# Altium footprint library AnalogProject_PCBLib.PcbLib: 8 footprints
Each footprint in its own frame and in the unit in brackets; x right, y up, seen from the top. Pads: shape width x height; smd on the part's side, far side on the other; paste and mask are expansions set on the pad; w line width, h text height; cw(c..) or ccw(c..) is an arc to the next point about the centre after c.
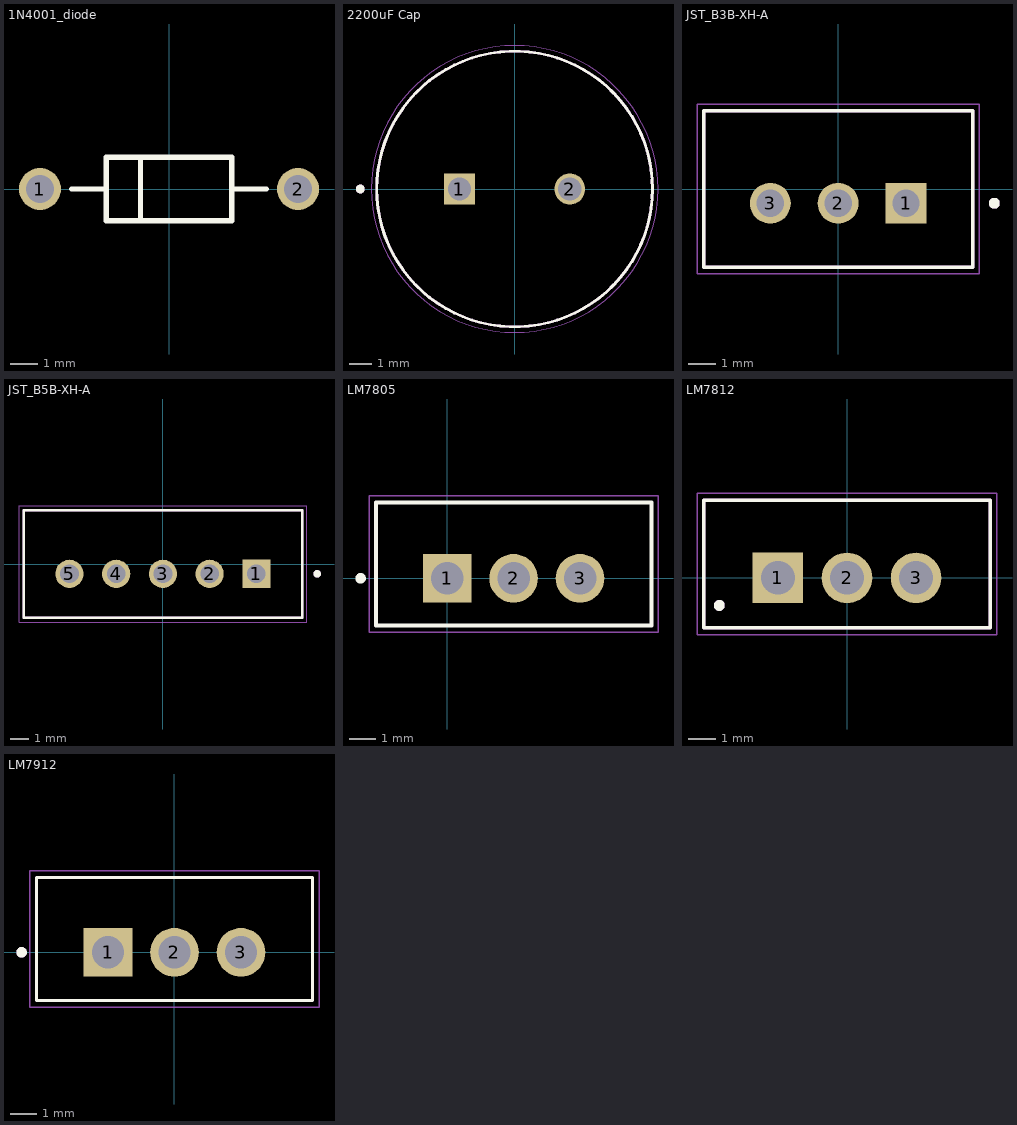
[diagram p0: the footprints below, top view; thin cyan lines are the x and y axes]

## 1N4001_diode [mm] "AXIAL, 2-Leads, Diameter 2.35mm"
height 2.35
pads (2):
  round 1.55 hole 1.05: 1(-4.77,0) 2(4.77,0)
Top Overlay:
  lines w0.2: -3.595,0 -2.325,0 ; -1.055,-1.175 -1.055,1.175 ; 2.325,0 3.595,0 ; -2.325,-1.175 2.325,-1.175 2.325,1.175 -2.325,1.175 -2.325,-1.175

## 2200uF Cap [mm]
pads (2):
  rect 1.4x1.4 hole 1.05: 1(-2.5,0)
  round 1.4 hole 1.05: 2(2.5,0)
Top Overlay:
  circle w0.127: c0,0 r6.25
  circle w0.2: c-7,0 r0.1
Mechanical 13:
  circle w0.127: c0,0 r6.25
  circle w0.2: c-7,0 r0.1
Mechanical 15:
  circle w0.05: c0,0 r6.5
3D body "step_temp.STEP": height 35, standoff -17, extent -6.25,-6.249 6.25,6.249

## JST_B3B-XH-A [mm]
height 7
pads (3):
  rect 1.508x1.508 / inner round 1.508 / far side rect 1.508x1.508 hole 1: 1(2.5,-0.525)
  round 1.508 hole 1: 2(0,-0.525) 3(-2.5,-0.525)
Top Overlay:
  circle w0.2: c5.75,-0.525 r0.1
  lines w0.127: -4.95,-2.875 4.95,-2.875 4.95,2.875 -4.95,2.875 -4.95,-2.875
Mechanical 13:
  circle w0.2: c5.75,-0.525 r0.1
  lines w0.127: -4.95,-2.875 4.95,-2.875 4.95,2.875 -4.95,2.875 -4.95,-2.875
Mechanical 15:
  lines w0.05: -5.2,-3.125 5.2,-3.125 5.2,3.125 -5.2,3.125 -5.2,-3.125
3D body "step_temp.STEP": height 7, standoff -3.4, extent -4.95,-2.875 4.95,2.875

## JST_B5B-XH-A [mm]
height 7
pads (5):
  rect 1.508x1.508 / inner round 1.508 / far side rect 1.508x1.508 hole 1: 1(5,-0.525)
  round 1.508 hole 1: 2(2.5,-0.525) 3(0,-0.525) 4(-2.5,-0.525) 5(-5,-0.525)
Top Overlay:
  circle w0.2: c8.25,-0.525 r0.1
  lines w0.127: -7.45,-2.875 -7.45,2.875 7.45,2.875 7.45,-2.875 -7.45,-2.875
Mechanical 13:
  circle w0.2: c8.25,-0.525 r0.1
  lines w0.127: -7.45,-2.875 -7.45,2.875 7.45,2.875 7.45,-2.875 -7.45,-2.875
Mechanical 15:
  lines w0.05: -7.7,-3.125 -7.7,3.125 7.7,3.125 7.7,-3.125 -7.7,-3.125
3D body "step_temp.STEP": height 7, standoff -3.4, extent -7.45,-2.875 7.45,2.875

## LM7805 [mm]
pads (3):
  rect 1.86x1.86 / inner round 1.86 / far side rect 1.86x1.86 hole 1.24: 1(0,0)
  round 1.86 hole 1.24: 2(2.54,0) 3(5.08,0)
Top Overlay:
  circle w0.2: c-3.31,0 r0.1
  lines w0.152: -2.73,-1.8 -2.73,2.9 7.81,2.9 7.81,-1.8 -2.73,-1.8
Mechanical 13:
  lines w0.127: -2.73,-1.8 -2.73,2.9 7.81,2.9 7.81,-1.8 -2.73,-1.8
Mechanical 15:
  lines w0.05: -2.98,-2.052 8.06,-2.052 8.06,3.148 -2.98,3.148 -2.98,-2.052
3D body "step_temp.STEP": height 20.4, standoff -9.94, extent -2.54,-2.143 7.62,2.207

## LM7812 [mm]
pads (3):
  rect 1.86x1.86 / inner round 1.86 / far side rect 1.86x1.86 hole 1.24: 1(-2.54,0)
  round 1.86 hole 1.24: 2(0,0) 3(2.54,0)
Top Overlay:
  circle w0.2: c-4.699,-1.016 r0.1
  lines w0.127: -5.27,-1.84 5.27,-1.84 5.27,2.86 -5.27,2.86 -5.27,-1.84
Mechanical 13:
  lines w0.127: -5.27,-1.84 5.27,-1.84 5.27,2.86 -5.27,2.86 -5.27,-1.84
  lines w0.2: -4.797,-1.036 cw(c-4.699,-1.016) -4.779,-1.076
Mechanical 15:
  lines w0.05: -5.52,-2.09 5.52,-2.09 5.52,3.11 -5.52,3.11 -5.52,-2.09
3D body "step_temp.STEP": height 15.49, standoff -13.84, extent -5.08,-2.286 5.08,2.413

## LM7912 [mm]
height 19.55
pads (3):
  rect 1.86x1.86 / inner round 1.86 / far side rect 1.86x1.86 hole 1.24: 1(-2.54,0)
  round 1.86 hole 1.24: 2(0,0) 3(2.54,0)
Top Overlay:
  circle w0.2: c-5.84,0 r0.1
  lines w0.127: -5.27,-1.84 5.27,-1.84 5.27,2.86 -5.27,2.86 -5.27,-1.84
Mechanical 13:
  circle w0.2: c-5.84,0 r0.1
  lines w0.127: -5.27,-1.84 5.27,-1.84 5.27,2.86 -5.27,2.86 -5.27,-1.84
Mechanical 15:
  lines w0.05: -5.52,-2.09 5.52,-2.09 5.52,3.11 -5.52,3.11 -5.52,-2.09
3D body "step_temp.STEP": height 15.49, standoff -13.84, extent -5.08,-2.349 5.08,2.349

## PCBComponent_1 [mm]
